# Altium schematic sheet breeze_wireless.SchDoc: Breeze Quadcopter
size A4; Author: myyerrol; Organization: Team MicroDynamics; Address1: NWPU; Address2: Xi'an; Address3: Shannxi; Address4: China; Revision: V0.1; SheetNumber: 5; SheetTotal: 5
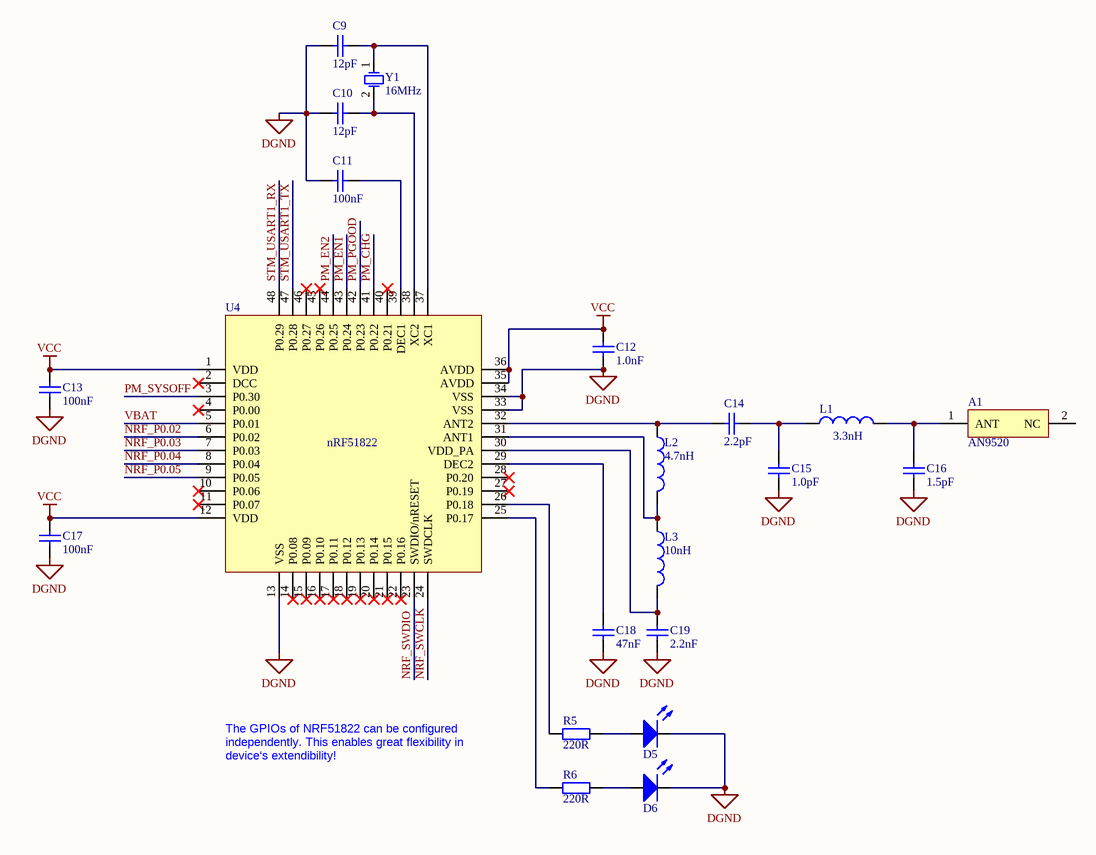
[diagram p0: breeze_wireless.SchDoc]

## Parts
A1  AN9520  [AN9520]
C9  value 12pF  [SMD-0603]  (hidden comment: CAP-0603)
C10  value 12pF  [SMD-0603]  (hidden comment: CAP-0603)
C11  value 100nF  [SMD-0603]  (hidden comment: CAP-0603)
C12  value 1.0nF  [SMD-0603]  (hidden comment: CAP-0603)
C13  value 100nF  [SMD-0603]  (hidden comment: CAP-0603)
C14  value 2.2pF  [SMD-0603]  (hidden comment: CAP-0603)
C15  value 1.0pF  [SMD-0603]  (hidden comment: CAP-0603)
C16  value 1.5pF  [SMD-0603]  (hidden comment: CAP-0603)
C17  value 100nF  [SMD-0603]  (hidden comment: CAP-0603)
C18  value 47nF  [SMD-0603]  (hidden comment: CAP-0603)
C19  value 2.2nF  [SMD-0603]  (hidden comment: CAP-0603)
D5  LED-0603  [SMD-0603]  (value not drawn)
D6  LED-0603  [SMD-0603]  (value not drawn)
L1  value 3.3nH  [SMD-0402]  (hidden comment: IND-0402)
L2  value 4.7nH  [SMD-0402]  (hidden comment: IND-0402)
L3  value 10nH  [SMD-0402]  (hidden comment: IND-0402)
R5  value 220R  [SMD-0603]  (hidden comment: RES-0603)
R6  value 220R  [SMD-0603]  (hidden comment: RES-0603)
U4  nRF51822  [QFN-48]
Y1  value 16MHz  [SMD-5032]  (hidden comment: XTAL-5032)

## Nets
DGND: C9.2 C10.2 C11.2 C12.2 C13.2 C15.2 C16.2 C17.2 C18.2 C19.2 D5.2(K) D6.2(K) U4.13(VSS) U4.33(VSS) U4.34(VSS)
VCC: C12.1 C13.1 C17.1 U4.1(VDD) U4.12(VDD) U4.35(AVDD) U4.36(AVDD)
NRF_P0.02: U4.6(P0.02)
NRF_P0.03: U4.7(P0.03)
NRF_P0.04: U4.8(P0.04)
NRF_P0.05: U4.9(P0.05)
NRF_SWCLK: U4.24(SWDCLK)
NRF_SWDIO: U4.23(SWDIO/nRESET)
PM_CHG: U4.41(P0.22)
PM_EN1: U4.43(P0.24)
PM_EN2: U4.44(P0.25)
PM_PGOOD: U4.42(P0.23)
PM_SYSOFF: U4.3(P0.30)
STM_USART1_RX: U4.48(P0.29)
STM_USART1_TX: U4.47(P0.28)
VBAT: U4.5(P0.01)
NetA1_1: A1.1(ANT) C16.1 L1.2
NetC9_1: C9.1 U4.37(XC1) Y1.1(OSC1)
NetC10_1: C10.1 U4.38(XC2) Y1.2(OSC2)
NetC11_1: C11.1 U4.39(DEC1)
NetC14_1: C14.1 L2.1 U4.32(ANT2)
NetC14_2: C14.2 C15.1 L1.1
NetC18_1: C18.1 U4.29(DEC2)
NetC19_1: C19.1 L3.2 U4.30(VDD_PA)
NetD5_1: D5.1(A) R5.2
NetD6_1: D6.1(A) R6.2
NetL2_2: L2.2 L3.1 U4.31(ANT1)
NetR5_1: R5.1 U4.26(P0.18)
NetR6_1: R6.1 U4.25(P0.17)

Not connected (* = marked no-connect by the designer): A1 2(NC); U4 2(DCC)* 4(P0.00)* 10(P0.06)* 11(P0.07)* 14(P0.08)* 15(P0.09)* 16(P0.10)* 17(P0.11)* 18(P0.12)* 19(P0.13)* 20(P0.14)* 21(P0.15)* 22(P0.16)* 27(P0.19)* 28(P0.20)* 40(P0.21)* 45(P0.26)* 46(P0.27)*

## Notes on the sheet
- The GPIOs of NRF51822 can be configured independently. This enables great flexibility in device‘s extendibility!

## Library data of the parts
A1 = AN9520: 2.4GHz Wireless Communication Antenna
C9-C19 = CAP-0603: Capacitor
D5 D6 = LED-0603: LED
L1-L3 = IND-0402: Inductor
R5 R6 = RES-0603: Resistor
U4 = nRF51822: Multiprotocol Bluetooth 4.0 low energy/2.4 GHz RF SoC
Y1 = XTAL-5032: Passive Crystal Oscillator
